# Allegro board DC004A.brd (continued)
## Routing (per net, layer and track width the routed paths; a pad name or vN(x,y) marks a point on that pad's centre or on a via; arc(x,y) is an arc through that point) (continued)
JESD_SYSREFP: length 5.2
  BOTTOM w0.152: R59.1 107.06,127.1 R62.1 106.07,127.1 105.88,126.91 105.49,126.91 104.71,127.68 103.24,127.68 103.13,127.79 U4.3
LMK04828_CSB: length 91.3
  TOP w0.152: SJP9.2 73.15,52.7 73.66,52.2 77.6,52.2 TP5.1
  L10_SIG-2 w0.152: v1(101.3,117.09) 101.27,74.48 v1(95.76,68.96)
  BOTTOM w0.152: v1(95.76,68.96) 95.76,59.82 94.49,58.55 94.49,55.88 92.96,54.36 79.88,54.36 77.72,52.2 TP5.1
  BOTTOM w0.279: U4.18 v1(101.3,117.09)
LMK04828_SYNC: length 4.1
  TOP w0.279: R97.2 132.08,93.73 v1(132.72,93.09)
LMK LOCKED:
  vias: v1(50.08,144.47)
LMK_CLKIN: length 6.1
  BOTTOM w0.279: R70.1 R71.1 J22.1
LMK_LMX_CLK: length 151.3
  TOP w0.152: SJP7.2 68.96,53.34 v1(68.96,58.2)
  TOP w0.279: v1(100.73,115.73) 80.54,115.73 75.06,121.22 75.06,125.34 68.55,131.85 62.41,131.85 61.93,132.33 v1(61.93,135)
  L10_SIG-2 w0.165: v1(61.93,135) 61.81,134.83 59.41,134.83 59.3,134.73 59,134.73 55.21,130.94 55.21,119.64 56.04,118.81 56.04,88.74 70.87,73.92 70.87,60.11 v1(68.96,58.2)
  BOTTOM w0.279: v1(61.93,135) 61.93,135.12 61.86,135.19 61.86,135.66 61.8,135.71 U3.16 ; U4.19 100.77,115.77 v1(100.73,115.73)
LMK_LMX_DATA: length 148.7
  L04_SIG-1 w0.14: v1(61.32,135.37) 61.32,134.8 62.23,133.88 68.7,133.88 77.64,124.94 77.64,119.2 85.71,111.13 95.43,111.13 99.67,115.37 v1(99.67,116.53)
  L10_SIG-2 w0.127: 72.17,53.75 72.17,74.06 64.73,81.5 64.73,132.42 62.48,134.67 62.48,135.19 62.2,135.48 61.43,135.48 v1(61.32,135.37)
  L10_SIG-2 w0.152: v1(71.12,52.7) 72.17,53.75
  BOTTOM w0.279: U3.17 61.3,135.38 v1(61.32,135.37) ; v1(99.67,116.53) 100.32,117.18 100.32,120.41 100.27,120.46 U4.20
LMK_SDO: length 117.2
  L10_SIG-2 w0.152: v1(105.16,69.47) 105.08,69.55 105.08,72.09
  L10_SIG-2 w0.165: 105.08,72.09 105.08,78.39 102.65,80.82 102.65,118.38 103.25,118.99 105.06,118.99 105.54,119.47 105.54,124.91 104.75,125.7 v1(104.75,126.44)
  BOTTOM w0.127: 79.12,50.16 80.01,51.05 95.12,51.05 97.92,53.85 97.92,67.56 99.31,68.96
  BOTTOM w0.152: 99.31,68.96 104.65,68.96 v1(105.16,69.47) ; 79.12,50.16 76.07,47.12 70.74,47.12 69.6,48.26 v1(69.6,49.02)
  BOTTOM w0.279: U4.5 104.4,126.79 v1(104.75,126.44)
LMX_CLKB: length 27.1
  L04_SIG-1 w0.14: v1(79.78,125.9) 79.78,120.01 v1(79.48,119.7)
  BOTTOM w0.279: C108.2 R52.2 64.32,131.69 69.75,126.26 76.58,126.26 76.94,125.9 v1(79.78,125.9)
LMX_CLKM: length 74
  BOTTOM w0.254: U3.22 57.96,137.61 arc(57.77,137.58) 57.61,137.47 arc(57.49,137.39) 57.34,137.36 R45.1 arc(56.71,137.47) 56.51,137.51 56.03,137.51 arc(56.01,137.51) 55.99,137.51 55.53,137.51 arc(55.24,137.45) 54.99,137.29 arc(54.71,137.1) 54.38,137.03 54.28,137.03 arc(53.92,137.1) 53.62,137.31 arc(53.39,137.46) 53.13,137.51 52.32,137.51 arc(51.94,137.44) 51.63,137.22 51.56,137.16 arc(51.35,137.02) 51.09,136.96 51.09,136.96 arc(50.69,137.04) 50.36,137.27 50.32,137.31 arc(50.09,137.46) 49.83,137.51 49.66,137.51 arc(49.3,137.44) 49,137.24 48.99,137.23 arc(48.77,137.08) 48.51,137.03 48.26,137.03 arc(47.97,137.09) 47.73,137.25 47.72,137.26 arc(47.45,137.44) 47.12,137.51 46.86,137.51 arc(46.65,137.47) 46.47,137.35 46.42,137.3 arc(46.07,137.07) 45.66,136.98 arc(45.32,137.05) 45.04,137.24 44.89,137.39 arc(44.65,137.48) 44.41,137.51 43.25,137.51 arc(41.97,137.26) 40.9,136.54 40.25,135.9 arc(40.07,135.63) 40.01,135.31 40.01,135.16 arc(39.95,134.87) 39.79,134.62 39.78,134.62 arc(39.49,134.42) 39.16,134.36 39.08,134.36 arc(38.74,134.29) 38.46,134.1 32.48,128.12 arc(32.41,128.02) 32.38,127.89 32.38,125.15 arc(31.83,123.8) 30.48,123.24 27.1,123.24 arc(25.57,122.94) 24.26,122.07 22.47,120.27 arc(20.75,117.69) 20.14,114.64 20.14,102.4 arc(20.23,101.93) 20.5,101.54 arc(20.69,101.26) 20.75,100.93 arc(20.69,100.6) 20.5,100.33 20.4,100.22 arc(20.22,100.14) 20.14,99.96 20.14,99.69 arc(20.22,99.29) 20.45,98.94 20.54,98.85 arc(20.7,98.62) 20.75,98.35 20.75,98.07 arc(20.7,97.81) 20.55,97.59 20.33,97.37 arc(20.19,97.05) 20.14,96.71 arc(20.32,96.29) 20.74,96.11 21,96.11 arc(21.1,96.13) 21.18,96.19 21.31,96.32 arc(21.39,96.37) 21.49,96.39 C50.1
LMX_CLKP: length 74
  BOTTOM w0.254: C51.1 21.49,95.12 arc(21.39,95.14) 21.31,95.2 21.18,95.33 arc(21.1,95.38) 21,95.4 20.74,95.4 arc(19.81,95.78) 19.43,96.71 19.43,114.64 arc(20.09,117.96) 21.97,120.78 23.76,122.57 arc(25.3,123.59) 27.1,123.95 30.48,123.95 arc(31.32,124.3) 31.67,125.15 31.67,127.89 arc(31.75,128.29) 31.98,128.63 38.39,135.04 39.33,135.98 40.39,137.04 arc(41.7,137.91) 43.25,138.22 56.5,138.22 arc(56.7,138.26) R44.1 57.35,138.37 arc(57.49,138.35) 57.6,138.27 arc(57.77,138.15) 57.98,138.11 U3.23
LMX_CSB: length 101.2
  L10_SIG-2 w0.127: v1(58.02,138.88) 60.13,136.77 65.54,136.77 66.65,135.66 66.65,131.15 65.97,130.48 65.97,87.23 78.2,75 78.2,56.47
  L10_SIG-2 w0.152: 78.2,56.47 74.43,52.7 v1(74.17,52.7)
  BOTTOM w0.127: v1(58.02,138.88) 58.28,138.61 U3.24
LMX_OSCM: length 46.8
  L10_SIG-2 w0.16: v1(69.61,135.13) 69.67,135.13 71.53,133.27 arc(72.06,132.48) 72.24,131.56 72.24,130.63 arc(72.46,129.51) 73.09,128.57 73.48,128.19 73.54,128.12 74.06,127.6 74.19,127.47 83.13,118.53 83.73,117.93 84.04,117.62 84.29,117.37 84.77,116.89 84.83,116.83 85.32,116.34 85.41,116.25 85.88,115.78 85.93,115.73 87.08,114.58 arc(89.09,113.24) 91.46,112.77 95.36,112.77 arc(96.4,113.2) 96.83,114.24 96.83,114.9 v1(96.88,114.94)
  BOTTOM w0.254: v1(69.61,135.13) 69.61,135.17 67.76,137.02 arc(67.33,137.3) 66.82,137.4 66.61,137.4 arc(66.5,137.42) 66.41,137.49 arc(66.27,137.58) 66.1,137.61 U3.9 ; C249.1 96.85,116.83 96.85,114.97 v1(96.88,114.94)
LMX_OSCP: length 47.3
  L10_SIG-2 w0.16: v1(96.12,114.94) 96.16,114.9 96.16,114.24 arc(95.93,113.67) 95.36,113.44 95.07,113.44 arc(94.97,113.46) 94.9,113.51 94.78,113.63 arc(94.6,113.75) 94.39,113.79 94.39,113.79 arc(94.19,113.75) 94.03,113.64 93.92,113.53 93.91,113.52 arc(93.82,113.46) 93.72,113.44 93.47,113.44 arc(93.37,113.46) 93.29,113.51 93.17,113.63 arc(92.96,113.77) 92.72,113.82 arc(92.46,113.77) 92.24,113.62 92.15,113.52 arc(92.05,113.46) 91.94,113.44 91.46,113.44 arc(89.35,113.86) 87.56,115.05 86.8,115.81 arc(86.75,115.88) 86.74,115.96 86.74,116.25 arc(86.69,116.46) 86.57,116.65 86.52,116.69 arc(86.31,116.84) 86.06,116.89 85.86,116.89 arc(85.73,116.91) 85.62,116.99 85.49,117.12 arc(85.42,117.23) 85.39,117.36 85.39,117.56 arc(85.34,117.8) 85.2,118.01 85.2,118.01 arc(85.04,118.12) 84.84,118.16 84.61,118.16 arc(84.5,118.19) 84.41,118.25 84.27,118.39 arc(84.19,118.5) 84.17,118.64 84.17,118.82 arc(84.11,119.09) 83.96,119.31 83.96,119.31 arc(83.77,119.44) 83.55,119.48 83.36,119.48 arc(83.14,119.53) 82.96,119.65 74.85,127.76 arc(74.78,127.86) 74.76,127.98 74.76,128.33 arc(74.74,128.43) 74.68,128.53 74.49,128.72 arc(74.4,128.77) 74.3,128.79 73.95,128.79 arc(73.83,128.82) 73.73,128.88 73.57,129.04 arc(73.08,129.77) 72.91,130.63 72.91,131.56 arc(72.68,132.74) 72.01,133.74 70.14,135.6 v1(70.14,135.67)
  BOTTOM w0.254: C250.1 96.14,116.83 96.14,114.97 v1(96.12,114.94) ; v1(70.14,135.67) 70.11,135.67 68.26,137.52 arc(67.6,137.96) 66.82,138.11 U3.8
LMX_SDO: length 104.4
  L10_SIG-2 w0.127: 73.34,52.64 76.97,56.27 76.97,62.76 75.99,63.74 75.99,71.92 65.41,82.51 65.41,135.5 64.62,136.28 60.47,136.28 59.19,135 57.44,135 v1(56.72,134.28)
  L10_SIG-2 w0.152: v1(71.12,49.02) 72.64,49.02 73.28,49.66 73.28,52.58 73.34,52.64
MASTER_BYPASS: length 3.8
  TOP w0.508: 80.39,39.37 79.07,40.69 SJP15.2
  vias: v1(80.14,36.96) v1(80.14,35.56) v1(80.64,36.2) v1(80.77,38.35) v1(81.28,39.37) v1(81.28,36.96) v1(81.28,35.56) v1(82.17,37.59) v1(82.27,39.12) v1(82.27,36.07)
MASTER_BYPASS1: length 10.2
  TOP w0.508: SJP16.3 87.86,44.3 v1(88.14,44.58) v1(85.98,44.58) v1(84.33,44.58) v1(82.93,44.58) v1(81.28,44.58) 81.1,44.4 SJP15.1
MUX_OUT: length 35.5
  TOP w0.279: v1(59.16,144.85) 57.87,146.14 49.72,146.14 48.56,144.97 48.56,135.29 50.05,133.79 56.24,133.79 56.76,133.28 57.46,133.28 57.74,133.56 v1(57.74,134.28)
  BOTTOM w0.254: R50.2 v1(59.16,144.85)
  BOTTOM w0.279: U3.20 57.75,134.28 v1(57.74,134.28)
NCOA0: length 102.5
  TOP w0.279: R11.1 v1(87.37,62.52)
  L04_SIG-1 w0.14: v1(44.58,76.07) 44.7,75.95 44.7,74.68 45.21,74.17 45.21,61.09
  L04_SIG-1 w0.152: 45.21,61.09 45.21,55.37 48.13,52.45 55.37,52.45 57.53,54.61 80.39,54.61 J7.2
  L10_SIG-2 w0.089: 36.7,88.39 36.32,88.77 36.32,89.79 35.94,90.17 35.94,91.31 35.56,91.69 34.16,91.69 33.91,91.95 33.91,101.73 34.43,102.24 v1(34.43,102.26)
  L10_SIG-2 w0.165: v1(44.58,76.07) 42.42,78.23 42.42,78.74 41.4,79.76 40.26,79.76 37.34,82.68 37.34,87.76 36.7,88.39 ; v1(87.37,62.52) 81.28,56.43 J7.2
NCOA1: length 89.8
  TOP w0.279: R12.1 v1(87.37,61.38)
  L10_SIG-2 w0.089: 37.72,88.39 36.96,89.15 36.96,92.58 36.83,92.71 35.18,92.71 34.93,92.96 34.93,100.58 34.43,101.08 v1(34.43,101.26)
  L10_SIG-2 w0.165: v1(48.77,75) 44.9,78.87 43.18,78.87 38.1,83.95 38.1,88.01 37.72,88.39 ; v1(87.37,61.38) 87.37,61.33 83.82,57.78 J7.4
  BOTTOM w0.152: v1(48.77,75) 56.64,75 57.09,75.45 60.25,75.45 60.7,75 73.03,75 73.03,74.8 76.71,71.12 81.79,71.12 83.82,69.09 83.82,66.42 85.6,64.64 85.6,63.15 v1(87.37,61.38)
NCOB0: length 84.6
  TOP w0.279: R17.1 v1(87.37,60.24)
  L10_SIG-2 w0.165: v1(87.37,60.24) 87.29,60.24 86.49,59.44 86.49,55.63 J7.6
  BOTTOM w0.152: v1(34.43,89.26) 34.43,89.08 34.57,89.08 34.57,84.56 35.56,83.57 35.56,73.41 36.45,72.52 45.08,72.52 45.19,72.42 54.01,72.42 55.72,74.13 56.98,74.13 57.47,74.62 59.88,74.62 60.64,73.85 72.96,73.85 76.33,70.48 81.53,70.48 82.04,69.98 82.04,68.58 83.31,67.31 83.31,64.52 84.71,63.12 85.09,63.12 86.71,61.5 86.71,60.89 v1(87.37,60.24)
NCOB1: length 86.9
  TOP w0.279: R18.1 v1(87.37,59.09)
  L10_SIG-2 w0.165: v1(87.37,59.09) 88.9,57.56 J7.8
  BOTTOM w0.152: v1(34.43,90.26) 34.29,90.12 34.29,89.72 34.24,89.72 33.97,89.45 33.97,89.07 34.24,88.8 34.29,88.8 34.29,84.67 34.29,84.33 35.28,83.34 35.28,73.29 35.31,73.26 35.31,72.39 35.56,72.14 54.9,72.14 55.79,73.02 73.03,73.02 76.2,69.85 80.13,69.85 80.39,70.1 80.77,70.1 80.79,70.08 80.95,70.08 81.66,69.37 81.66,68.45 82.55,67.56 82.55,64.39 84.14,62.8 84.14,59.5 84.54,59.09 v1(87.37,59.09)
OSC_M: length 17.8
  L04_SIG-1 w0.124: v1(91.47,125.42) 91.25,125.2 90.35,125.2 89.3,124.15 89.3,122.44 90.27,121.47 93.6,121.47 96.41,118.65 96.41,117.19 96.15,116.93 v1(95.55,116.93)
  BOTTOM w0.152: U4.41 92.71,125.29 92.6,125.18 91.71,125.18 v1(91.47,125.42)
OSC_P: length 17.9
  L04_SIG-1 w0.124: v1(91.47,124.66) 91.23,124.89 90.47,124.89 89.61,124.03 89.61,122.56 90.4,121.77 93.72,121.77 94.32,121.17 94.68,121.17 94.84,121.01 94.84,120.65 95.15,120.35 95.51,120.35 95.67,120.2 95.67,119.83 95.97,119.53 96.33,119.53 96.49,119.37 96.49,119.01 96.72,118.78 96.72,117.19 97.05,116.86 v1(97.49,116.86)
  BOTTOM w0.152: U4.40 92.71,124.79 92.6,124.9 91.71,124.9 v1(91.47,124.66)
OSCI: length 8.4
  TOP w0.152: Y2.2 50.78,67.07 C184.1 50.8,65.33 50.95,65.18 51.56,65.18 51.71,65.33 52.84,65.33 53.41,64.75 53.63,64.75 53.73,64.85 U8.2
OSCINN: length 4.7
  BOTTOM w0.152: C150.2 89.11,126.87 C152.2 90.1,126.87 90.29,126.68 92.6,126.68 92.71,126.79 U4.44
OSCINP: length 4.7
  BOTTOM w0.152: C145.2 89.11,126.21 C146.2 90.1,126.21 90.29,126.4 92.6,126.4 92.71,126.29 U4.43
OSCN: length 2.4
  BOTTOM w0.152: C149.2 86.21,126.87 R88.2 R93.1 87.78,126.92 C150.1
OSCO: length 8.4
  TOP w0.152: U8.3 53.73,64.35 53.61,64.47 53.3,64.47 52.72,65.05 51.83,65.05 51.68,64.9 50.98,64.9 50.8,64.72 50.8,62.99 50.78,62.97 Y2.1
OSCP: length 2.3
  BOTTOM w0.152: C144.2 86.16,126.21 R82.2 R85.1 87.78,126.16 C145.1
OVRA: length 58.3
  TOP w0.152: R225.1 96.27,65.91 97.28,66.93 v1(97.28,73.41)
  BOTTOM w0.152: 133.99,76.58 133.86,76.58 133.22,77.22 126.75,77.22 126.11,77.85 121.16,77.85 118.36,75.06 116.46,75.06 115.7,75.82 111.63,75.82 109.22,73.41 v1(97.28,73.41)
OVRA0: length 156.5
  TOP w0.152: v1(98.93,71.25) 98.3,70.61 98.3,63.75 95.58,61.04 D12.1
  L04_SIG-1 w0.127: 116.9,72.71 116.9,72.83 121.28,77.22 123.32,77.22 129.03,82.93 136.4,82.93 137.8,81.53 137.8,80.39 v1(135.25,77.85)
  L04_SIG-1 w0.14: v1(91.71,72.26) 91.27,72.7 91.27,74.4 88.33,77.33 62.88,77.33 v1(59.63,74.08) ; 115.38,71.18 116.9,72.71
  L04_SIG-1 w0.152: 115.38,71.18 99,71.18 v1(98.93,71.25) 98.87,71.18 92.78,71.18 v1(91.71,72.26)
  L10_SIG-2 w0.089: 35.78,102.62 v1(35.42,102.26)
  L10_SIG-2 w0.165: 35.78,102.62 35.92,102.76 35.92,103.11 37.34,104.52 50.71,104.52 55.03,100.2 55.03,87.81 59.63,83.21 v1(59.63,74.08)
OVRA1: length 87.8
  L04_SIG-1 w0.14: v1(91.71,71.12) 90.43,72.39 90.43,73.4 87.32,76.52 63.87,76.52 60.93,73.57 58.91,73.57 v1(58.44,74.04)
  L10_SIG-2 w0.089: 36.83,102.62 36.88,102.57 36.88,101.98 36.68,101.78 35.89,101.78 35.42,101.31 v1(35.42,101.26)
  L10_SIG-2 w0.165: 36.83,102.62 36.83,103.51 37.46,104.14 49.92,104.14 52.46,101.6 52.46,87.62 58.44,81.64 v1(58.44,74.04)
OVRB: length 61.1
  TOP w0.279: R226.1 v1(80.39,71.63)
  BOTTOM w0.152: v1(80.39,71.63) 81.41,71.63 84.52,74.74 94.3,74.74 96.39,72.64 110.87,72.64 111.25,73.03 111.25,74.55 112.14,75.44 115.32,75.44 116.2,74.55 118.62,74.55 121.41,77.34 125.48,77.34 126.94,75.88 133.41,75.88 133.99,75.31
OVRB0: length 199.3
  TOP w0.152: R145.2 v1(93.86,69.97) 95.12,68.71 95.12,66.64 94.84,66.36 86.48,66.36 85.21,67.64 85.21,70.99 81.75,74.44 75.88,74.44 74.62,73.18 56.19,73.18 v1(51.9,68.89) ; v1(113.16,70.36) 113.16,66.67 114.68,65.15 114.68,57.02 113.63,55.97 v1(113.46,55.97)
  L04_SIG-1 w0.152: v1(93.86,69.97) 95,69.97 95.12,69.85 97.92,69.85 98.42,70.36 v1(113.16,70.36)
  L10_SIG-2 w0.152: 35.31,88.14 35.31,89.14 v1(35.42,89.26) ; v1(113.46,55.97) 113.7,55.97 115.06,54.61 127.64,54.61 130.52,57.49 140.09,57.49 140.09,57.49 140.33,57.49 140.88,58.04 144.4,58.04 146.43,60.07 146.43,71.37 145.67,72.14 140.97,72.14 140.72,72.39 135.38,72.39 135.06,72.07 133.67,72.07 132.59,73.15 132.59,73.66 133.6,74.68 135.76,74.68 136.78,75.69 136.78,76.7 139.06,78.99 v1(139.06,79.12)
  L10_SIG-2 w0.165: v1(51.9,68.89) 43.88,68.89 42.16,70.61 37.21,70.61 34.8,73.03 34.8,79.63 35.31,80.14 35.31,88.14
OVRB1: length 80.4
  L04_SIG-1 w0.14: v1(51.05,74.04) 56.87,74.04
  L04_SIG-1 w0.152: 56.87,74.04 58.42,72.49
  L04_SIG-1 w0.165: 58.42,72.49 60.76,72.49 64.06,75.79 81.42,75.79 v1(84.39,72.82)
  L10_SIG-2 w0.089: 35.81,88.39 35.81,90.04 35.6,90.26 v1(35.42,90.26)
  L10_SIG-2 w0.165: v1(91.71,68.83) 90.82,68.83 86.83,72.82 v1(84.39,72.82) ; v1(51.05,74.04) 50.93,73.91 49.02,73.91 47.94,72.83 46.42,72.83 44.7,71.12 37.59,71.12 35.81,72.9 35.81,88.39
PD: length 32
  TOP w0.152: v1(36.45,86.49) 36.43,87.73 U1.P9
  L04_SIG-1 w0.14: J8.2 41.66,66.42 43.18,67.95 43.18,85.22 41.91,86.49 36.83,86.49
  L04_SIG-1 w0.152: 36.83,86.49 v1(36.45,86.49)
  BOTTOM w0.152: R21.1 J8.2
PG_RX1: length 17.5
  TOP w0.279: v3(136.53,110.87) 136.32,111.07 R104.2 134.24,113.87 122.76,113.87 J26.2
PG_U14: length 32.6
  TOP w0.279: v1(59.94,32) 59.18,32 58.42,31.24 U14.20
  BOTTOM w0.279: v1(59.94,32) 53.34,25.4 53.34,18.54 51.69,16.89 42.04,16.89 v1(40.51,15.37)
PLL2 LOCKED:
  vias: v1(50.08,136.09)
PRSNT_M2C_L: length 3.1
  TOP w0.279: R106.1 133.38,111.87 133.99,111.26 v1(133.99,109.6)
RFOUTB_M: length 3.9
  BOTTOM w0.279: C110.1 R49.1 58.98,134.32 60.3,135.65 U3.19
RFOUTB_P: length 4.1
  BOTTOM w0.279: C108.1 R48.1 61.73,134.4 61.7,134.4 61.56,134.54 61.39,134.72 61.14,134.72 60.86,135 60.86,135.06 60.77,135.14 60.77,136.31 U3.18
RFOUTBM: length 7.7
  TOP w0.279: J20.1 54.94,130.75 arc(55.43,130.85) 55.86,131.13 55.98,131.26 55.99,131.25 arc(56.48,131.58) 57.05,131.69 v1(58.98,131.69)
  BOTTOM w0.279: v1(58.98,131.69) C110.2
SLAVE_BYPASS:
  vias: v1(80.52,17.27) v1(81.41,18.16) v1(81.53,17.02) v1(82.27,17.91) v1(82.27,16.38) v1(82.27,14.86) v1(82.42,17.14) v1(82.42,15.62) v2(78.23,14.81)
SLAVE_BYPASS1: length 31.5
  TOP w0.279: v1(91.69,18.16) 91.69,19.18 92.08,19.56 92.58,19.56 93.73,20.7 99.7,20.7 100.84,19.56 100.84,16 102.74,14.1 106.81,14.1 108.71,12.19 R222.2
  TOP w0.508: v1(85.6,13.59) 85.47,13.72 81.15,13.72 80.64,14.22 80.64,14.43 SJP17.1
  vias: v1(86.36,14.35) v1(86.87,13.59) v1(87.76,14.35) v1(88.39,13.59) v1(89.03,14.48) v1(89.92,13.59) v1(90.04,18.16) v1(90.81,18.16) v1(90.81,14.48) v1(91.57,16.89) v1(91.57,15.88) v1(91.57,14.73) v1(91.57,13.59)
STAT 0:
  vias: v1(50.08,141.68)
STAT 1:
  vias: v1(50.08,138.88)
SYNC: length 124.8
  TOP w0.279: TP4.1 115.82,71.5 123.57,71.5 R98.1 ; v1(107.67,125.42) 109.04,125.42 110.62,123.84 110.62,119.13 116.71,113.03 v1(119.2,113.03) ; v1(129.47,92.41) 129.2,92.41 R97.1
  L04_SIG-1 w0.14: v1(129.47,92.41) 129.47,86.92 116.46,73.91 TP4.1 112.14,72.64 107.07,72.64 106.69,73.02 106.69,86.83 109.89,90.03 109.89,111 111.92,113.03 v1(119.2,113.03)
  BOTTOM w0.279: v1(107.67,125.42) 107.52,125.27 105.06,125.27 104.03,126.29 U4.6
SYNC_N: length 145.2
  TOP w0.254: R36.1 12.94,63.5 13.1,63.65 16.88,63.65 arc(16.9,63.65) 16.92,63.65 19.42,63.65 arc(20.11,63.51) 20.7,63.12 21.03,62.79 arc(21.79,62.28) 22.68,62.1 42.28,62.1 arc(43.11,62.27) 43.82,62.74 44.45,63.37 arc(45.01,64.22) 45.21,65.21 45.21,72.8 arc(45.39,73.71) 45.91,74.49 47.12,75.69 arc(48.07,76.33) 49.19,76.55 100.33,76.55 arc(101.08,76.4) 101.71,75.98 arc(102.84,75.23) 104.17,74.96 108.85,74.96 v1(108.88,74.94)
  L04_SIG-1 w0.16: v1(108.88,74.94) 108.93,74.98 109.26,74.98 arc(110.16,75.16) 110.92,75.67 113.59,78.34 arc(114.14,79.16) 114.33,80.13 114.33,81.79 arc(114.45,82.4) 114.8,82.92 119.88,88 arc(120.8,88.62) 121.89,88.83 122.53,88.83 arc(123.59,89.05) 124.49,89.65 129.39,94.55 arc(130.92,95.57) 132.73,95.93 134.96,95.93 v1(135.25,95.63)
SYNC_P: length 145.2
  TOP w0.254: R35.1 12.94,64.52 13.1,64.36 16.88,64.36 arc(16.91,64.36) 16.94,64.36 19.42,64.36 arc(20.38,64.17) 21.2,63.62 21.54,63.29 arc(22.06,62.94) 22.68,62.81 42.28,62.81 arc(42.84,62.93) 43.31,63.24 43.95,63.88 arc(44.36,64.49) 44.5,65.21 44.5,72.8 arc(44.74,73.98) 45.41,74.99 46.61,76.19 arc(47.8,76.99) 49.19,77.26 100.33,77.26 arc(101.35,77.06) 102.21,76.48 arc(103.11,75.88) 104.17,75.67 108.85,75.67 v1(108.88,75.7)
  L04_SIG-1 w0.16: v1(108.88,75.7) 108.93,75.65 109.26,75.65 arc(109.9,75.78) 110.45,76.15 113.11,78.81 arc(113.52,79.42) 113.66,80.13 113.66,81.79 arc(113.83,82.66) 114.32,83.39 119.41,88.48 arc(120.55,89.24) 121.89,89.51 122.53,89.51 arc(123.33,89.67) 124.01,90.12 128.92,95.02 arc(130.66,96.19) 132.73,96.6 134.96,96.6 v1(135.25,96.9)
SYNC_SE: length 257.2
  TOP w0.279: R98.2 126.62,73.03 129.69,73.03 129.96,73.29 130.39,73.29 130.66,73.03 133.73,73.03 v1(133.99,72.77)
  L04_SIG-1 w0.152: v1(26.67,44.32) 26.67,68.22 26.49,68.4 26.49,68.76 26.67,68.94 26.67,82.42 28.91,84.66 28.91,91.47 29.16,91.72 31.65,91.72 31.88,91.95 31.88,102.59 31.34,103.12 30.35,103.12 29.59,103.89 v1(24.26,103.89)
  L10_SIG-2 w0.165: v1(133.99,72.77) 134.62,73.41 145.41,73.41 147.07,71.75 147.07,59.44 145.16,57.53 140.78,57.53 140.45,57.2 140.21,57.2 139.97,57.2 131.11,57.2 127.76,53.85 112.52,53.85 109.73,51.05 109.73,38.61 107.06,35.94 96.65,35.94 93.73,33.02 81.66,33.02 80.26,31.62 74.17,31.62 73.28,32.51 37.34,32.51 36.32,33.53 27.56,33.53 25.65,35.43 25.65,38.1 26.16,38.61 26.16,43.81 v1(26.67,44.32)
  BOTTOM w0.152: 24.26,102.36 v1(24.26,103.89)
SYNC_SW: length 23.9
  TOP w0.279: U14.4 v1(40.89,27.43)
  BOTTOM w0.279: v1(40.51,11.56) 37.85,11.56 36.83,12.57 36.83,17.02 40.77,20.95 40.77,24.51 41.28,25.02 41.28,26.67 40.89,27.05 v1(40.89,27.43)
SYNCSE: length 4.6
  BOTTOM w0.152: R25.2 R26.1 27.36,102.36 27.94,101.78 28.91,101.78 v1(29.42,101.26)
SYS+: length 2
  TOP w0.279: C45.2 26.67,92.2 28.37,92.2 U1.L1
SYS-: length 2
  TOP w0.279: C47.2 26.67,91.31 28.37,91.31 U1.M1
SYSREF+: length 8.3
  BOTTOM w0.254: R76.1 107.53,119.25 R78.1 107.55,119.93 107.55,121.48 arc(107.13,122.49) 106.11,122.91 104.44,122.91 104.31,122.79 U4.13
SYSREF-: length 8.3
  BOTTOM w0.254: R77.1 106.86,119.25 R79.1 106.84,119.94 106.84,120.15 arc(106.73,120.42) 106.47,120.52 106.29,120.52 arc(106.07,120.62) 105.97,120.84 arc(106.06,121.04) 106.26,121.12 106.48,121.12 arc(106.73,121.23) 106.84,121.48 arc(106.62,121.99) 106.11,122.2 104.37,122.2 104.28,122.29 U4.14
SYSREFM: length 116
  TOP w0.254: v1(23.52,91.36) 23.54,91.38 25.05,91.38 arc(25.31,91.33) C47.1 ; v1(46.74,116.01) 46.95,115.8 arc(47.03,115.74) 47.13,115.72 49.56,115.72 arc(50.66,115.5) 51.59,114.88 51.59,114.88 arc(53.28,113.75) 55.27,113.36 104.54,113.36 arc(106.17,114.03) 106.84,115.65 106.84,116.21 v1(106.81,116.24)
  L10_SIG-2 w0.16: v1(23.52,91.36) 23.47,91.4 21.14,91.4 arc(19.57,92.05) 18.91,93.63 18.91,95.71 arc(19.2,97.16) 20.02,98.39 arc(20.63,98.8) 21.36,98.94 22.38,98.94 arc(23.59,99.45) 24.09,100.66 24.09,101.07 arc(24.29,102.05) 24.85,102.88 29.21,107.25 arc(29.99,107.77) 30.91,107.95 42.65,107.95 arc(42.83,107.99) 42.99,108.09 43.31,108.41 arc(43.4,108.51) 43.49,108.61 arc(43.54,108.68) 43.6,108.76 arc(43.79,109.1) 43.92,109.46 arc(43.97,109.76) 43.99,110.05 43.99,114.07 arc(44,114.16) 44,114.25 arc(44.15,114.73) 44.43,115.13 arc(45.07,115.55) 45.81,115.7 46,115.7 arc(46.4,115.78) v1(46.74,116.01)
  BOTTOM w0.254: R77.2 106.81,117.93 R80.1 106.84,117.85 106.84,116.26 v1(106.81,116.24)
SYSREFP: length 116
  TOP w0.254: v1(107.58,116.24) 107.55,116.21 107.55,115.65 arc(106.67,113.53) 104.54,112.65 61.94,112.65 61.94,112.65 58.21,112.65 arc(57.92,112.59) 57.68,112.43 arc(57.36,112.22) 56.98,112.14 56.68,112.14 arc(56.16,112.25) 55.71,112.54 arc(55.5,112.62) 55.27,112.65 arc(53.01,113.1) 51.08,114.38 arc(50.39,114.85) 49.56,115.01 47.13,115.01 arc(47.03,114.99) 46.95,114.94 v1(46.74,114.73) ; v1(23.52,92.12) 23.54,92.09 24.96,92.09 arc(25.27,92.15) C45.1
  L10_SIG-2 w0.16: v1(23.52,92.12) 23.47,92.07 21.14,92.07 arc(20.04,92.53) 19.58,93.63 19.58,95.71 arc(19.82,96.9) 20.5,97.92 arc(20.89,98.18) 21.36,98.27 22.38,98.27 arc(24.07,98.97) 24.77,100.66 24.77,101.07 arc(24.91,101.79) 25.32,102.41 29.68,106.77 arc(30.25,107.15) 30.91,107.28 42.65,107.28 arc(43.09,107.37) 43.46,107.62 44.37,108.53 arc(44.6,108.86) 44.68,109.26 44.68,110.38 arc(44.7,110.51) 44.77,110.61 44.9,110.74 44.9,110.74 45.04,110.87 arc(45.18,111.09) 45.24,111.35 arc(45.18,111.64) 45.01,111.89 arc(44.95,111.96) 44.89,112.03 arc(44.77,112.33) 44.89,112.64 45.09,112.83 arc(45.18,112.97) 45.21,113.13 45.21,113.24 arc(45.18,113.4) 45.09,113.53 44.88,113.75 arc(44.75,113.94) 44.7,114.17 arc(44.76,114.43) 44.91,114.66 arc(45.32,114.93) 45.82,115.03 46,115.03 arc(46.4,114.95) v1(46.74,114.73)
  BOTTOM w0.254: 107.55,117.85 107.58,117.88 R76.2 ; 107.55,117.85 R81.1 ; 107.55,117.85 107.55,116.26 v1(107.58,116.24)
TCRIT1: length 13.8
  TOP w0.152: U2.4 12.3,126.14 R28.2 R37.2 13.08,128.02 5.33,128.02 3.94,129.41 TP1.1
TCRIT2: length 7.9
  TOP w0.152: U2.7 7.7,125.64 R27.2 7.7,125.65 6.73,126.62 4.32,126.62 TP2.1
TDI: length 17.9
  BOTTOM w0.102: 128.52,74.8 138.3,74.8 J25.D30
  BOTTOM w0.279: 128.52,74.8 124.39,74.8 123.37,75.82 J27.1
TDIODE+: length 70
  TOP w0.152: R40.2 16.75,125.34 18.43,125.34 18.67,125.09 18.67,124.21
  L04_SIG-1 w0.089: v1(29.42,90.26) 29.79,89.89 30.26,89.89 30.27,89.88 30.58,89.88 30.59,89.89 31.26,89.89 31.27,89.88 31.58,89.88 31.59,89.89 32.26,89.89 32.27,89.88 32.58,89.88 32.59,89.89 32.74,89.89 33.02,90.17 33.02,91.59 33.17,91.74 33.83,91.74 33.99,91.9 33.99,102.62
  L04_SIG-1 w0.124: 18.67,124.21 18.67,125.2 18.79,125.32 19.93,125.32 20.05,125.2 20.05,124.97 20.18,124.84 21.12,124.84 21.24,124.97 21.24,125.2 21.37,125.32 22.31,125.32 22.43,125.2 22.43,125.02 22.58,124.87 23.48,124.87 23.63,125.02 23.63,125.2 23.75,125.32 26.26,125.32 29.34,128.4 30.85,128.4 30.98,128.27 30.98,128.14 31.13,127.99 32.02,127.99 32.17,128.14 32.17,128.27 32.29,128.4 36.07,128.4 37.47,127 37.47,121.03 35.69,119.25 35.69,108.97 34.29,107.57 34.29,102.92 33.99,102.62
TDIODE-: length 70
  TOP w0.152: R42.2 16.75,125.62 18.43,125.62 18.67,125.86 J17.1
  L04_SIG-1 w0.089: 34.98,102.62 34.98,92.02 34.7,91.74 34.24,91.74 33.83,91.34 33.83,90.07 33.4,89.63 32.86,89.63 32.85,89.62 32.7,89.62 32.69,89.61 32.16,89.61 32.15,89.62 31.7,89.62 31.69,89.61 31.35,89.61 30.61,88.87 30.23,88.87 29.84,89.26 v1(29.42,89.26)
  L04_SIG-1 w0.124: 34.98,102.62 34.59,103 34.59,107.44 35.99,108.84 35.99,119.13 37.77,120.9 37.77,127.13 36.19,128.7 29.21,128.7 26.14,125.63 18.79,125.63 18.67,125.75 J17.1
TDIODEN: length 3.6
  TOP w0.152: U2.3 13.33,125.64 C44.2 13.64,125.93 13.97,125.6 14.73,125.6 R42.1
TDIODEP: length 3.5
  TOP w0.152: U2.2 13.44,125.14 C44.1 13.68,124.93 14.07,125.32 14.76,125.32 R40.1
TDO: length 17.4
  BOTTOM w0.102: 128.52,73.28 138.56,73.28 J25.D31
  BOTTOM w0.279: J27.2 128.52,73.28
TMP461_SMBCLK: length 154
  TOP w0.152: U2.9 9.57,124.64 9.02,124.08 8.42,124.08 v1(7.7,123.35)
  L04_SIG-1 w0.14: 7.37,60.83 7.37,123.02 v1(7.7,123.35) ; 38.23,36.32 39.62,36.32 41.15,34.8 54.48,34.8 56.26,36.58 56.26,40.51 57.4,41.66 57.4,50.04 58.04,50.67 58.04,51.18 59.82,52.96 v1(59.82,53.09)
  L04_SIG-1 w0.152: 7.37,60.83 7.37,55.75 12.15,50.97 17.23,50.97 19.3,48.89 19.3,43.81 20.32,42.8 20.32,38.61 21.34,37.59 24.84,37.59 27.76,34.67 36.58,34.67 38.23,36.32
TMP461_SMBDAT: length 169.2
  TOP w0.152: v1(7.7,124.5) 8.55,124.5 9.18,125.14 U2.8
  TOP w0.279: R113.2 60.96,52.2 62.1,51.05 v1(65.79,51.05)
  L04_SIG-1 w0.14: v1(7.7,124.5) 6.98,123.78 6.98,123.65 6.86,123.78 6.5,123.78 6.26,123.53 6.26,123.18 6.5,122.93 6.86,122.93 6.98,123.06 6.98,55.24 15.75,46.48 ; v1(65.79,51.05) 65.66,51.05 64.39,49.78 64.39,35.31 63.37,34.29 38.23,34.29
  L04_SIG-1 w0.152: 15.75,46.48 15.75,38.35 18.29,35.81 21.46,35.81 21.97,35.31 26.66,35.31 27.63,34.34 30.81,34.34 31.37,33.78 37.72,33.78 38.23,34.29
  BOTTOM w0.279: R110.2 66.04,51.31 v1(65.79,51.05)
TMSP+: length 13
  TOP w0.279: J14.1 9.96,70.36 arc(10.91,69.96) 11.3,69.01 R34.1
TMSP-: length 13
  TOP w0.279: R38.1 11.3,59.02 arc(10.91,58.06) 9.94,57.66 J15.1
TMSTP+: length 46.2
  L04_SIG-1 w0.089: 27.56,100.12 27.57,100.12 27.61,100.08 28.01,100.08 28.03,100.09 arc(28.24,100.14) v1(28.43,100.26)
  L04_SIG-1 w0.16: v1(12.32,65.53) 12.32,64.5 arc(12.37,64.39) 12.48,64.34 14.16,64.34 arc(18,65.94) 19.6,69.78 19.6,81.46 arc(19.9,82.99) 20.77,84.28 23.49,87 arc(24.5,88.52) 24.86,90.31 24.86,93.4 arc(24.94,93.84) 25.19,94.21 25.31,94.33 arc(25.43,94.51) 25.48,94.73 25.48,98.82 arc(25.55,99.21) 25.78,99.55 26.04,99.81 arc(26.38,100.04) 26.77,100.12 27.56,100.12
TMSTP-: length 46.3
  L04_SIG-1 w0.089: 27.56,99.44 27.58,99.42 27.62,99.46 27.94,99.46 arc(28.2,99.41) v1(28.43,99.26)
  L04_SIG-1 w0.16: 27.56,99.44 26.77,99.44 arc(26.63,99.42) 26.52,99.34 26.25,99.07 arc(26.17,98.96) 26.15,98.82 26.15,94.73 arc(26.05,94.26) 25.79,93.86 25.67,93.74 arc(25.56,93.58) 25.53,93.4 25.53,90.31 arc(25.12,88.27) 23.96,86.53 21.24,83.81 arc(20.52,82.73) 20.27,81.46 20.27,69.78 arc(18.48,65.46) 14.16,63.67 12.48,63.67 arc(12.37,63.63) 12.32,63.51 v1(12.32,62.48)
V_BUS: length 25.8
  BOTTOM w0.508: v1(29.84,39.88) 29.84,42.55 40.37,53.07 46.46,53.07 JP6.3
  vias: v1(27.43,40.26) v1(27.43,38.1) v1(27.94,38.99) v1(28.45,39.62) v1(28.45,38.1) v1(28.83,38.86) v1(29.84,38.25)
VA11:
  vias: v1(15.88,87.93) v1(15.88,86.66) v1(16.64,87.3) v1(17.4,87.93) v1(17.4,86.66) v1(18.29,87.5) v1(18.29,86.36) v1(19.3,87.5) v1(19.3,86.36) v1(25.88,106.05) v1(29.42,97.26) v1(29.42,94.26) v1(30.43,99.26) v1(30.43,98.26) v1(30.43,97.26) v1(30.43,96.26) v1(30.43,95.26) v1(30.43,94.26) v1(30.43,93.26) v1(30.43,92.26) v1(83.82,20.45) v1(83.85,19.56) v1(84.96,20.45) v1(84.96,19.56) v1(85.6,18.16) v1(85.6,16.76) v1(85.6,15.49) v1(85.85,20.32) v1(86.23,18.67) v1(86.36,16.26) v1(86.49,19.43) v1(86.49,18.16) v1(86.74,20.32) v1(86.74,17.65) v1(87.25,16) v1(87.5,20.32) v1(87.5,15.49)
VA19: length 21.8
  TOP w0.254: C77.1 v1(27.18,89.41)
  BOTTOM w0.203: R19.1 37.72,71.37 34.93,68.58 v1(26.92,68.58)
  BOTTOM w0.254: C70.1 28.45,93.28 v1(28.43,93.26)
  BOTTOM w0.279: 28.63,87.16 27.81,86.34 ; 27.81,86.34 27.81,86.44 ; 27.81,86.34 C83.1 ; 27.83,87.19 27.81,87.18 27.81,86.44 ; 27.81,86.44 27.06,87.19
  BOTTOM w0.381: R20.1 v1(36.58,125.73)
  BOTTOM w0.508: v1(25.53,100.41) 26.31,100.41 26.82,99.9 C81.1
  vias: v1(27.05,87.76) v1(27.05,86.74) v1(27.05,86.11) v1(27.81,87.76) v1(28.43,98.26) v1(28.83,45.59) v1(29.42,100.26) v1(29.42,99.26) v1(29.42,98.26) v1(29.42,93.26) v1(29.42,92.26) v1(29.42,91.26) v1(30.43,100.26) v1(30.43,91.26) v1(31.42,100.26) v1(31.42,91.26) v1(32.43,100.26) v1(32.43,91.26) v1(81.28,49.66) v1(81.28,48.64) v1(82.17,49.15) v1(82.17,48.13) v1(83.82,49.66) v1(83.82,48.64) v1(84.71,49.15) v1(84.71,48.13) v1(86.36,49.66) v1(86.36,48.64) v1(87.25,49.15) v1(87.25,48.13) v1(88.9,49.66) v1(88.9,48.64) v1(89.79,49.15) v1(90.81,48.51) v1(91.69,49.02) v1(91.95,48.01) v1(92.71,49.53) v1(93.34,48.51) v1(94.23,49.02) v1(95,48.13) v1(95.12,38.1) v1(95.25,46.48) v1(95.25,44.32) v1(95.25,41.15) v1(95.25,39.37) v1(95.5,49.53) v1(95.5,42.42) v1(95.89,48.51) v1(95.89,40.89) v1(96.01,43.05) v1(96.01,38.1) v1(96.01,37.08) v1(96.14,46.99) v1(96.14,39.5) v1(96.27,45.21) v1(96.77,49.02) v1(96.9,42.93) v1(96.9,38.48) v1(96.9,36.96) v1(97,40.26) v1(97.16,47.88) v1(97.16,45.72) v1(97.16,41.4) v1(97.16,39.5) v1(97.28,44.32)
VADJ_RX: length 102.6
  TOP w0.279: R107.1 133.22,60.58 v1(133.99,61.34) ; v1(135.25,62.61) 134.77,62.13 134.77,61.59 134.73,61.56 134.73,61.13 134.77,61.09 134.77,60.3 135.51,59.56 135.51,58.17 135.13,57.78 133.48,57.78 132.21,56.52 118.75,56.52 117.35,55.12 PP17.1 ; v1(139.06,113.41) 137.44,111.79 R104.1
  L04_SIG-1 w0.14: v1(136.53,61.34) 138.18,59.69 145.54,59.69 148.59,62.74 148.59,69.88 148.55,69.93 148.55,70.28 148.59,70.32 148.59,72.42 148.55,72.47 148.55,72.82 148.59,72.86 148.59,82.2 148.55,82.25 148.55,82.6 148.59,82.64 148.59,84.74 148.55,84.79 148.55,85.14 148.59,85.18 148.59,94.78 148.55,94.82 148.55,95.17 148.59,95.22 148.59,97.32 148.55,97.36 148.55,97.71 148.59,97.76 148.59,106.71 148.55,106.76 148.55,107.11 148.59,107.15 148.59,109.25 148.55,109.3 148.55,109.65 148.59,109.69 148.59,111.12 146.3,113.41 v1(139.06,113.41)
  vias: v1(137.8,62.61)
VBIAS_VCO: length 2.4
  BOTTOM w0.305: C116.2 67.23,140.61 U3.3
VBIASBANK: length 2.6
  BOTTOM w0.127: v1(56.77,140.1) 56.77,140.13 C111.2
  BOTTOM w0.305: U3.27 58.05,140.11 57.69,140.48 C111.2
VD11: length 0.5
  BOTTOM w0.254: C93.1 38.43,91.36 v1(38.43,91.26)
  BOTTOM w0.279: C84.1 v1(37.42,100.26)
  vias: v1(37.03,68.91) v1(37.42,91.26) v1(37.92,68.78) v1(38.43,100.26) v1(38.81,69.17) v1(39.42,100.26) v1(39.42,99.26) v1(39.42,98.26) v1(39.42,97.26) v1(39.42,96.26) v1(39.42,95.26) v1(39.42,94.26) v1(39.42,93.26) v1(39.42,92.26) v1(39.42,91.26) v1(43.31,102.21) v1(45.19,125.67) v1(92.2,20.45) v1(95,18.67) v1(95.12,19.3) v1(95.12,16.76) v1(95.12,15.62) v1(95.5,17.65) v1(96.01,16.76) v1(96.01,15.62) v1(96.14,19.3) v1(96.14,18.16) v1(96.65,17.53) v1(96.9,15.75) v1(97,19.05) v1(97.03,18.16) v1(97.16,16.89)
VIO_B_M2C_RX:
  vias: v3(131.44,61.34) v3(132.72,62.61)
VPHY: length 4.3
  TOP w0.305: v1(53.21,64.01) 53.34,63.88 53.46,63.88 53.49,63.85 U8.4
  BOTTOM w0.254: v1(53.21,64.01) 53.09,64.14 53.09,64.39 ; FB12.2 53.09,64.39 ; 53.09,64.39 C169.1 C168.1
VREF_VCO1: length 2.5
  BOTTOM w0.305: U3.29 58.29,141.11 57.51,141.9 v1(57.51,142.54)
VREF_VCO2: length 2.8
  TOP w0.381: v1(62.3,143.36) 61.52,143.36 C115.2
  BOTTOM w0.305: U3.36 v1(62.3,143.36)
VREG_VCO: length 1.1
  BOTTOM w0.254: v1(63.38,143.49) 63.3,143.41 U3.38
VREGIN: length 26.2
  TOP w0.305: v1(62.03,67.69) 62.04,67.69 62.37,67.27 62.37,66.83 62.31,66.77 U8.50
  L10_SIG-2 w0.165: v1(62.03,67.69) 61.26,68.45 56.26,68.45 55.63,69.09 53.21,69.09 47.9,63.77 47.9,61.89 46.85,60.85 46.85,58.31 JP6.2
  BOTTOM w0.254: v1(62.03,67.69) C176.1
VTUNE: length 5.8
  BOTTOM w0.254: R55.2 C122.1
  BOTTOM w0.279: U3.35 61.8,143.12 61.78,143.14 61.78,143.57 61.8,143.59 61.8,144.16 62.22,144.58 62.33,144.58 62.37,144.53 62.8,144.53 62.85,144.58 64.46,144.58 64.5,144.53 64.63,144.53 C122.1
Y1_N: length 11.1
  BOTTOM w0.152: R91.1 84.2,126.89 R92.1 83.21,126.89 83.02,126.7 82.06,126.7 81.02,127.75 81.02,128.64 81.17,128.79 81.26,128.79 81.42,128.95 81.42,129.25 81.26,129.4 81.17,129.4 81.02,129.56 81.02,130.32 81.17,130.47 81.99,130.47 82.15,130.62 Y1.4
Y1_P: length 11.1
  BOTTOM w0.152: Y1.5 79.61,130.62 79.76,130.47 80.58,130.47 80.74,130.32 80.74,127.63 81.94,126.42 83.02,126.42 83.21,126.23 R84.1 84.2,126.23 R83.1
YO1_N: length 0.7
  BOTTOM w0.152: C149.1 R91.2
YO1_P: length 0.7
  BOTTOM w0.152: C144.1 R83.2
N18340257: length 0.5
  BOTTOM w0.254: v1(29.46,30.1) R148.2
N19884870: length 7.4
  BOTTOM w0.127: v3(77.07,133.67) 77.07,130.04 v1(77.12,129.99)
  BOTTOM w0.279: v3(77.07,133.67) 77.12,133.62 v1(77.12,129.99)
  vias: v1(77.07,128.98) v1(77.07,127.83) v1(78.08,128.98) v1(78.34,127.83)
N19884947: length 4.1
  BOTTOM w0.279: Y1.2 v1(79.61,145.36)
N19887754: length 2.1
  TOP w0.254: v1(92.18,125.8) 92.05,125.93 FB8.2
  BOTTOM w0.279: U4.42 92.19,125.79 v1(92.18,125.8)
N19887756: length 9.4
  TOP w0.381: FB9.1 v1(92.18,128.77) 92.18,129.48 v1(92.05,129.61)
  TOP w0.508: v1(90.65,130.75) 90.25,130.35 90.25,129.46 89.08,128.29 89.08,126.94 89.59,126.44 FB8.1
  BOTTOM w0.127: U4.47 93.44,128.29
  BOTTOM w0.279: 93.44,128.29 92.66,128.29 v1(92.18,128.77)
  vias: v1(90.65,133.29) v1(90.65,131.9) v1(91.39,132.66)
N19887760: length 3.5
  TOP w0.381: FB10.2 95.99,129.86 C165.1 v1(96.24,130.63)
  BOTTOM w0.127: U4.53 96.27,129.62 96.24,129.64 v1(96.24,130.63)
N19887762: length 3.2
  TOP w0.381: v1(101.96,131.01) 101.96,130.29 101.7,130.04 C166.1
  BOTTOM w0.279: v1(101.96,131.01) 101.77,130.82 U4.64
N19887789: length 67.4
  L04_SIG-1 w0.14: v1(84.99,142.29) 86.21,141.07 86.21,122.49 89.71,118.99 94.59,118.99 v1(94.95,118.71)
  L10_SIG-2 w0.165: v1(53.82,143.58) 56.38,143.58 56.74,143.94 60.8,143.94 61.96,142.78 68.67,142.78 68.93,143.03 80.21,143.03 80.96,142.29 v1(84.99,142.29)
  BOTTOM w0.279: v1(94.95,118.71) 94.77,118.82 U4.31 ; v1(53.82,143.58) 52.54,143.58 R102.2
N19887795: length 66.6
  L04_SIG-1 w0.14: v1(93.07,131.01) 91.94,132.14 91.94,133.52 87.62,137.84 87.62,141.66 86.33,142.95 75.66,142.95 72.39,146.22 52.47,146.22 51.21,144.96 51.21,134.89 v1(51.65,134.45)
  BOTTOM w0.127: U4.48 93.44,128.79
  BOTTOM w0.279: v1(93.07,131.01) 93.07,129.16 93.44,128.79 ; v1(51.65,134.45) R103.2
N19887804: length 56.2
  L10_SIG-2 w0.165: v1(54.21,139.64) 54.21,140.02 55.3,141.11 56.62,141.11 57.39,140.34 58.23,140.34 59.48,139.09 59.48,138.07 60.3,137.25 64.24,137.25 64.77,137.78 74.44,137.78 76.67,135.55 93.66,135.55 94.84,134.37 94.84,133.43 95.65,132.62 97.77,132.62 v1(99.27,131.12)
  BOTTOM w0.127: U4.59 99.27,129.62
  BOTTOM w0.279: v1(54.21,139.64) 52.42,139.64 R101.2 ; 99.27,129.62 v1(99.27,131.12)
N19887822: length 58.7
  L10_SIG-2 w0.165: v1(54.46,141.42) 54.46,141.47 54.96,141.97 57.47,141.97 58.43,141.02 59.6,141.02 60.13,141.55 65.8,141.55 66.95,140.41 84.36,140.41 88.65,136.11 97.83,136.11 99.21,134.73 99.21,133.59 100.29,132.52 100.29,131.13 99.58,130.42 v1(98.72,130.42)
  BOTTOM w0.279: v1(98.72,130.42) 98.77,130.37 U4.58 ; R100.2 51.71,141.68 52.51,140.88 53.91,140.88 v1(54.46,141.42)
N19887828: length 2.1
  TOP w0.381: v2(103.51,123.29) 103.13,123.29 C163.1
  BOTTOM w0.127: 102.6,123.29 U4.12
  BOTTOM w0.279: v2(103.51,123.29) 102.6,123.29
N19887830: length 2.5
  BOTTOM w0.127: 102.6,123.79 U4.11
  BOTTOM w0.203: 104.01,123.79 102.6,123.79
  BOTTOM w0.279: v1(104.62,124.4) 104.01,123.79
N19887836: length 4.6
  TOP w0.381: v1(103.47,124.29) 102.73,124.29 C154.2 ; C155.2 v1(93.45,120.72)
  BOTTOM w0.127: U4.10 102.6,124.29
  BOTTOM w0.254: v1(92.1,122.66) 92.14,122.66 92.26,122.79 93.44,122.79 ; 93.45,121.28 v1(93.45,120.72) ; 102.6,124.29 v1(103.47,124.29)
  BOTTOM w0.279: U4.36 93.44,122.79 ; U4.33 93.46,121.29 93.45,121.28
N19887876: length 2
  TOP w0.279: FB7.2 v1(92.18,124.33)
  BOTTOM w0.127: U4.39 93.44,124.29
  BOTTOM w0.254: v1(92.18,124.33) 92.21,124.33 92.25,124.29 93.44,124.29
N19887878: length 3.3
  TOP w0.508: FB9.2 90.91,127.92 91.48,127.34 v1(92.09,127.34)
  BOTTOM w0.127: U4.45 93.44,127.29
  BOTTOM w0.254: v1(92.09,127.34) 92.14,127.29 93.44,127.29
N19887910: length 1.1
  BOTTOM w0.279: U4.21 99.77,119.6 v1(99.8,119.58)
N19887912: length 1.1
  BOTTOM w0.279: U4.17 101.77,120.02 v1(102.08,119.7)
N19887930: length 1.2
  BOTTOM w0.279: v1(97.51,119.58) 97.27,119.82 U4.26
N19955835: length 12.9
  TOP w0.305: U13.4 24.32,35.74 25.02,35.04 25.02,30.99 26.42,29.59 26.42,25.91 26.8,25.53 v1(27.66,25.53)
N20234062: length 1.7
  TOP w0.279: C118.2 60.61,143.02 v1(60.8,143.22)
  BOTTOM w0.279: U3.33 v1(60.8,143.22)
N20239082: length 5.2
  TOP w0.279: v1(58.27,141.96) 57.99,141.83 54.98,141.83 54.64,142.18 R51.2
  BOTTOM w0.279: U3.30 58.72,141.61 v1(58.27,141.96)
N20251064: length 0.8
  BOTTOM w0.254: C120.2 R56.1
N20251377: length 1.7
  BOTTOM w0.229: R55.1 C121.1
  BOTTOM w0.254: R54.2 R55.1
N20258125: length 0.8
  TOP w0.381: D2.1 v1(58.5,144.44)
N20381922: length 1.9
  TOP w0.279: R130.2 53.19,58.84 53.21,58.82 53.64,58.82 53.66,58.84 U8.14
N20381931: length 3.8
  TOP w0.254: v1(52.58,62.87) 53,62.87 53.03,62.84 54.47,62.84 U8.6
  BOTTOM w0.254: v1(52.58,62.87) 53,62.87 53.03,62.84 53.45,62.84 53.48,62.87 R122.2
N20382558: length 3.5
  TOP w0.279: U9.4 78.97,68.01 R131.2 79.83,65.87 R123.2
N20382827: length 6.7
  TOP w0.152: R117.1 11.85,46.75 11.85,45.17 10.76,44.09 9.76,44.09 9.49,43.81 J31.3
N20382847: length 6.7
  TOP w0.152: J31.2 9.49,44.62 9.74,44.37 10.64,44.37 11.57,45.29 11.57,45.66 11.43,45.8 11.32,45.8 11.18,45.93 11.18,46.12 11.32,46.25 11.42,46.25 11.57,46.4 11.57,46.7 R116.1
N20392160:
  vias: v1(7.37,45.41) v1(8.15,45.41) v1(9.02,45.41) v1(13.46,40.39) v1(13.46,39.12) v1(13.59,43.18) v1(13.59,41.78) v1(14.2,38.58) v1(14.73,43.94) v1(14.73,42.42) v1(14.73,41.15) v1(14.73,40) v1(14.83,38.98) v1(14.86,38.23)
N20393078: length 1.7
  TOP w0.279: v1(52.45,73) 51.97,72.52 D7.2
N20442573: length 2.3
  TOP w0.279: R13.2 J7.1
N20442576: length 2.3
  TOP w0.279: R14.2 J7.3
N20442579: length 2.3
  TOP w0.279: R15.2 J7.5
N20442582: length 2.3
  TOP w0.279: R16.2 J7.7
N20446174: length 28.7
  L04_SIG-1 w0.089: 29.08,102.62 29.42,102.27 v1(29.42,102.26)
  L04_SIG-1 w0.14: TP9.1 16.26,117.6 16.26,106.3 19.3,103.25 28.45,103.25 29.08,102.62
N20447902: length 30.9
  TOP w0.152: R37.1 20.83,128.4 24,125.22 26.67,125.22 29.84,128.4 40.78,128.4 D1.2
N20475697: length 3.6
  TOP w0.279: U11.14 84.94,61.21 86.25,62.52 R138.1
N20475701: length 3.4
  TOP w0.279: U11.13 85,60.56 85.81,61.38 R139.1
N20475713: length 3.2
  TOP w0.279: U11.12 85.11,59.91 85.43,60.24 R140.1
N20475725: length 3.2
  TOP w0.279: R141.1 85.22,59.09 85.05,59.26 U11.11
N20475883: length 3.1
  TOP w0.279: U11.9 86.34,57.96 R142.1
N20476138: length 4.1
  TOP w0.508: R142.2 91.42,57.95 SJP14.1
N20477206: length 3.6
  TOP w0.279: U10.14 51.01,38.69 R133.1
N20477210: length 3.4
  TOP w0.279: U10.13 51.51,38.04 R134.1
N20477222: length 3.2
  TOP w0.279: U10.12 52,37.39 R135.1
N20477234: length 6.2
  TOP w0.279: R136.1 51.31,36.58 51.14,36.74 v1(50.38,36.74) U10.11
  BOTTOM w0.279: R132.2 50.27,39.24 50.55,38.96 50.55,36.91 v1(50.38,36.74)
N20477346: length 19.7
  TOP w0.152: U10.3 42.59,38.69 41.66,39.62 41.66,42.67 49.66,50.67 49.66,52.2 50.29,52.83 SJP3.2
N20477348: length 21.3
  TOP w0.127: v1(44.83,38.35) 44.52,38.04 U10.4
  TOP w0.152: v1(51.94,46.61) 51.94,52.2 SJP4.2
  L10_SIG-2 w0.127: 47.24,45.72 44.83,43.31 v1(44.83,38.35)
  L10_SIG-2 w0.152: 47.24,45.72 48.13,46.61 v1(51.94,46.61)
N20477350: length 24.3
  TOP w0.127: v1(45.85,38.23) 45.01,37.39 U10.5
  TOP w0.152: v1(53.09,45.72) 53.59,46.23 53.59,52.2 SJP5.2
  L10_SIG-2 w0.127: 51.05,45.72 49.78,44.45 46.61,44.45 45.21,43.05 45.21,38.86 v1(45.85,38.23)
  L10_SIG-2 w0.152: v1(53.09,45.72) 51.05,45.72
N20477352: length 29.3
  TOP w0.127: U10.6 v1(45.55,36.74)
  TOP w0.152: v1(55.37,38.61) 55.37,52.32 55.88,52.83 SJP6.2
  BOTTOM w0.127: 53.85,38.48 53.72,38.35 53.21,38.35 51.82,36.96 51.82,35.56 51.31,35.05 47.24,35.05 v1(45.55,36.74)
  BOTTOM w0.152: 53.85,38.48 55.25,38.48 v1(55.37,38.61)
N20477392: length 3.1
  TOP w0.279: R137.1 49.24,35.43 U10.9
N20478124: length 0.2
  TOP w0.152: U7.4 v1(67.06,51.88)
N20479286: length 3.6
  TOP w0.279: U12.14 89.38,70.95 R143.1
N20479288: length 3.4
  TOP w0.279: R144.1 89.87,70.3 U12.13
N20479290: length 3.2
  TOP w0.279: R145.1 90.37,69.65 U12.12
N20479292: length 3.2
  TOP w0.279: R146.1 90.52,69 U12.11
N20479340: length 3.1
  TOP w0.279: R147.1 90.68,67.7 U12.9
N20479396: length 1.6
  TOP w0.279: R147.2 93.33,67.69 SJP13.1
N20523656: length 84.2
  L10_SIG-2 w0.089: v1(36.43,101.26) 35.98,100.81 35.2,100.81 34.98,101.04 34.98,102.54 35.05,102.62
  L10_SIG-2 w0.165: TP10.1 23.24,124.33 36.96,124.33 37.97,125.35 40.89,125.35 41.53,125.98 42.55,125.98 43.43,126.87 54.23,126.87 54.92,126.18 54.92,121.92 53.21,120.21 53.21,105.54 52.71,105.03 37.34,105.03 35.05,102.74 35.05,102.62
N20560674:
  vias: v1(139.06,66.42) v1(139.06,63.88) v1(139.06,61.34) v1(140.34,62.61)
N20560927: length 17.5
  TOP w0.279: J26.1 125.44,112.39 128.45,109.39 133.1,109.39 133.62,108.86 137.06,108.86 v1(139.06,110.87)
N20597236: length 2
  TOP w0.279: R108.1 J30.2
N20601243: length 4.9
  TOP w0.279: D10.1 109.98,63.55 109.46,63.02 109.46,61.65 109.15,61.34 U15.7
N20601382: length 3.4
  TOP w0.279: D11.1 101.73,62.85 101.96,62.61 U15.1
N20601403:
  vias: v1(109.98,67.06)
N20601859:
  vias: v1(101.73,67.06)
N20602433: length 5.6
  TOP w0.279: U15.5 C14.2 R184.1 111.94,58.8 112.26,59.12 D9.2
N20603216: length 4.4
  TOP w0.279: D12.2 R31.1 C3.2 U15.3
N20603624: length 10.4
  TOP w0.279: R33.1 C4.2 R30.2 109.09,60.07 U15.6 106.05,60.07 104.78,61.34 U15.2
N20606076: length 1.7
  BOTTOM w0.254: R20.2 J9.1
N20606250: length 2.4
  BOTTOM w0.152: R19.2 J8.1
N20759391: length 5.6
  TOP w0.279: R197.1 R198.2 C261.2 24.77,150.75 U16.9
N20760406: length 5.6
  TOP w0.279: R199.1 R200.2 C266.2 25.53,136.53 U17.9
N20770678: length 6.5
  TOP w0.508: SJP17.3 76.2,13.69 77.98,11.91 v1(77.98,10.16) v1(77.98,9.02)
  vias: v1(73.91,7.77) v1(73.91,6.38) v1(75.82,7.77) v1(75.82,6.38) v1(77.6,7.26) v1(79.38,10.16) v1(79.38,9.02) v1(79.38,6.35) v1(79.5,7.26) v1(81.34,9.91) v1(81.34,8.64) v1(81.34,7.37) v1(81.34,6.1) v1(81.34,4.83)
N20770696: length 2
  TOP w0.381: C272.1 81.34,12.31 U19.1
N20770708: length 2
  TOP w0.279: U19.15 C273.1
N20770710:
  vias: v1(95.95,8.64) v1(95.95,7.37) v1(95.95,6.1) v1(95.95,4.83) v1(97.28,8) v1(97.28,6.73) v1(97.28,5.46) v1(98.6,9.91) v1(98.68,8.51) v1(98.81,4.83) v1(98.81,3.43) v1(99.06,11.05) v1(99.19,6.22) v1(100.46,10.92) v1(100.84,5.59) v1(100.84,3.81) v1(101.37,4.7) v1(101.85,1.52) v1(101.98,10.92) v1(101.98,5.59) v1(101.98,3.81) v1(102.62,6.35) v1(102.62,2.67) v1(103.51,10.92) v1(105.16,10.92) v1(106.68,10.92)
N20770722: length 5.2
  TOP w0.279: 95.95,2.29 97.66,2.29 98.42,1.52 R203.1
N20770740: length 2
  TOP w0.279: U19.7 R204.1
N20770762: length 22.9
  TOP w0.279: U19.10 v1(97.54,3.56)
  BOTTOM w0.279: v1(97.54,3.56) 94.49,3.56 92.41,1.47 82.09,1.47 79.38,4.19 v1(79.38,5.33)
N20770834: length 0.8
  TOP w0.279: v1(98.04,11.05) 97.66,11.05 ; v1(98.04,12.19) 97.66,12.19
  vias: v1(95.5,14.1) v1(95.63,12.57) v1(95.95,11.18) v1(96.9,12.57) v1(97.03,14.1) v1(97.92,14.22) v1(98.42,13.46)
N20771140: length 9.2
  TOP w0.279: R191.1 63.88,10.79 v1(64.26,10.41) ; v1(60.07,10.41) 59.05,11.43 U18.17
  BOTTOM w0.279: v1(60.07,10.41) 60.96,11.3 63.37,11.3 v1(64.26,10.41)
N20771180: length 1.6
  TOP w0.279: 62.36,14.22 61.98,13.84 R201.2
N20771182: length 3.6
  TOP w0.279: R201.1 59.94,12.45 ; 59.94,12.45 59.69,12.7 U18.18 ; 59.94,12.45 C271.1
N20771289: length 2.4
  TOP w0.279: U18.20 57.99,15.44 58.42,15.88 59.82,15.88 R190.2
N20771323: length 8.5
  TOP w0.254: R223.2 40.72,16.18 39.57,16.18 38.86,15.47 R196.2
  TOP w0.279: R223.2 R193.2 41.66,13.97 U18.2
N20771329: length 2.3
  TOP w0.279: U18.3 R195.1
N20771355: length 2.1
  TOP w0.279: C258.1 59.44,14.86 58.55,13.97 U18.19
N20771381: length 3.3
  TOP w0.279: 57.99,10.16 58.55,10.16 60.2,8.51 C251.1
N20771385:
  vias: v1(57.99,8.89) v1(57.99,7.62) v1(57.99,6.35) v1(57.99,5.08) v1(57.99,3.81) v1(59.82,4.95) v1(59.82,3.81) v1(60.96,4.95) v1(60.96,3.81) v1(61.85,5.97) v1(61.85,4.45) v1(62.1,3.56) v1(62.69,5.21) v1(63.5,5.97) v1(63.5,4.45) v1(63.75,3.56)
N20772111: length 8.6
  TOP w0.279: v1(63.75,26.42) 63.75,27.94 R211.1 ; U14.17 59.05,27.43 v1(60.07,26.42)
  BOTTOM w0.279: v1(60.07,26.42) 60.96,25.53 62.87,25.53 v1(63.75,26.42)
N20772147: length 1.6
  TOP w0.279: 62.36,30.23 61.98,29.84 R215.2
N20772149: length 3.6
  TOP w0.279: R215.1 59.94,28.45 ; 59.94,28.45 C216.1 ; 59.94,28.45 59.69,28.7 U14.18
N20772286: length 4.1
  TOP w0.254: R212.2 40.69,30.94 arc(40.56,31.13) R214.2
  TOP w0.279: U14.2 41.66,29.97 R212.2
N20772300: length 2.3
  TOP w0.279: U14.3 R213.2
N20772322: length 2.1
  TOP w0.279: U14.19 58.88,29.97 C215.1
N20772348: length 3.1
  TOP w0.279: U14.16 58.17,26.16 60.2,24.13
N20772352:
  vias: v1(57.91,19.05) v1(57.99,24.89) v1(57.99,23.62) v1(57.99,22.35) v1(57.99,21.08) v1(57.99,19.81) v1(59.44,19.05) v1(60.2,20.95) v1(60.2,19.94) v1(60.83,19.05) v1(61.85,21.97) v1(61.85,20.45) v1(62.23,19.05) v1(62.69,21.21) v1(63.5,21.97) v1(63.5,20.45) v1(63.63,19.05)
N20774965: length 13.3
  BOTTOM w0.508: v1(81.34,31.11) 79.5,32.96 79.5,35.43 78.05,36.88 78.05,41.66 v2(77.04,42.67)
  vias: v1(79.38,27.56) v1(81.34,29.84) v1(81.34,28.57) v1(81.34,27.3) v1(81.34,26.04)
N20775006: length 2.4
  TOP w0.279: U20.1 81.34,33.9 C211.1
N20775018: length 2
  TOP w0.279: U20.15 C210.1
N20775020: length 15.3
  TOP w0.279: C127.1 v1(98.68,29.84)
  BOTTOM w0.508: v2(91.92,43.31) 91.92,41.55 92.46,41.02 92.46,33.34 v1(95.95,29.84)
  vias: v1(95.95,28.57) v1(95.95,27.3) v1(95.95,26.04) v1(97.47,29.84) v1(97.47,28.57) v1(97.47,27.3) v1(97.47,26.04) v1(98.6,31.11) v1(98.68,27.94) v1(98.68,26.54) v1(99.06,32.26) v1(99.7,27.05) v1(99.7,25.15) v1(100.36,26.16) v1(100.84,22.99) v1(101.09,27.05) v1(101.09,25.27) v1(101.09,24)
N20775032: length 4.1
  TOP w0.279: U20.9 99.31,23.49 R216.1
N20775050: length 2
  TOP w0.279: U20.7 R217.1
N20775064: length 24.1
  TOP w0.279: v1(97.28,24.77) U20.10
  BOTTOM w0.279: v1(79.38,26.54) 79.38,25.78 80.39,24.77 80.39,22.61 81.15,21.84 93.6,21.84 96.52,24.77 v1(97.28,24.77)
N20775144:
  vias: v1(95.12,33.02) v1(95.95,32.38) v1(96.39,33.02) v1(97.03,35.31) v1(97.03,33.91) v1(97.16,32.38) v1(98.04,33.4) v1(98.04,32.26) v1(98.17,35.05) v1(98.93,35.05)
N20776452: length 1.5
  TOP w0.508: SJP16.2 89.89,42.06 v1(90.04,41.91)
  vias: v1(90.04,39.88) v1(90.04,38.86) v1(90.81,39.88) v1(90.81,38.86) v1(91.69,39.88) v1(91.69,38.86)
N20809211: length 2.2
  TOP w0.279: 65.66,63.75 65.25,63.35 U8.44
N20814533: length 2.4
  TOP w0.279: R224.1 41.66,11.43 U18.4
N20837548: length 5.8
  TOP w0.152: SJP7.3 69.66,53.78 69.66,58.48 R118.2
N20837573: length 7.5
  TOP w0.152: SJP8.3 71.12,58.17 R119.2
N20837587: length 8.4
  TOP w0.152: SJP9.3 72.64,55.37 72.26,55.75 72.26,57.91 70.99,59.18 R120.2
N20837623: length 10.4
  TOP w0.152: R121.2 71.37,62.61 72.01,61.98 72.01,59.05 73.53,57.53 73.53,56.26 74.17,55.63 SJP10.3
N20837793: length 19.4
  TOP w0.279: v1(65.89,62.85) 64.99,62.85 64.97,62.87 64.54,62.87 64.52,62.85 U8.43
  L10_SIG-2 w0.152: 67.69,51.05 67.69,50.55 68.71,49.53 70.61,49.53 v1(71.12,50.04)
  L10_SIG-2 w0.165: 67.69,51.05 67.69,61.05 v1(65.89,62.85)
N20837816: length 15.3
  L10_SIG-2 w0.152: 68.2,50.8 68.96,50.04 v1(69.6,50.04)
  L10_SIG-2 w0.165: v1(66.67,63.75) 68.2,62.23 68.2,50.8
N20965250: length 1.6
  TOP w0.152: R137.2 SJP2.1
N198851401: length 0.7
  BOTTOM w0.279: C131.2 88.7,128.98 R66.1
N198852420: length 1
  BOTTOM w0.279: R63.1 94.21,116.45 C128.2

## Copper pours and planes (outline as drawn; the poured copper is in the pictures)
1.538V on TOP: 69.6,1.02 69.6,3.94 67.56,3.94 67.56,8.25 61.6,8.25 61.6,11.05 62.74,11.05 62.74,9.27 67.56,9.27 67.56,11.56 64.64,11.56 64.64,12.83 67.56,12.83 67.56,17.65 75.31,17.65 75.95,18.29 77.47,18.29 77.47,15.24 75.31,13.08 72.01,13.08 72.01,5.84 76.33,5.84 76.45,5.71 76.45,3.3 74.3,3.3 74.3,1.02
1.538V on L08_PWR-2: 69.6,1.02 69.6,3.94 67.56,3.94 67.56,8.25 61.6,8.25 61.6,11.05 62.74,11.05 62.74,9.27 67.56,9.27 67.56,11.56 64.64,11.56 64.64,12.83 67.56,12.83 67.56,17.65 75.31,17.65 75.31,13.08 72.01,13.08 72.01,2.79 74.3,2.79 74.3,1.02
3.3VCLK on TOP, L06_PWR-1: 28.07,147.7 23.75,147.7 23.75,146.3 22.1,146.3 22.1,149.86 28.19,149.86 28.19,150.24 36.32,150.24 36.32,147.7 31.62,147.7 31.62,144.15 28.07,144.15
3.3VLMX on TOP: 28.83,133.48 24.38,133.48 24.38,132.08 22.86,132.08 22.86,135.64 28.96,135.64 28.96,136.02 37.08,136.02 37.08,133.48 35.69,133.48 35.69,131.95 32.38,131.95 32.38,129.92 28.83,129.92
3.3VLMX on L06_PWR-1: 28.83,133.48 24.51,133.48 24.51,132.08 22.86,132.08 22.86,135.64 28.96,135.64 28.96,136.02 37.08,136.02 37.08,133.48 35.56,131.95 32.38,131.95 32.38,129.92 28.83,129.92
5.0V_IN on BOTTOM (solid shape): 25.84,25.17 22.03,25.17 22.03,29.69 25.84,29.69
5.0V_IN on TOP: 14.1,33.68 11.35,33.68 11.35,23.83 25.32,23.83 25.75,24.26 25.75,29.48 24.35,30.88 24.35,31.94 23.28,33.01 22.06,33.01 21.38,33.68 21.38,35.48 21.59,35.69 23.11,35.69 23.11,36.83 22.86,37.08 14.48,37.08 14.1,36.7
5.0V_IN on BOTTOM: 6.35,37.59 6.35,24.13 25.78,24.13 25.78,57.53 25.65,57.66 16.51,57.66 16.26,57.4 16.26,40 16.26,40 16.26,38.26 15.59,37.59
5.0V_IN on L08_PWR-2: 14.28,37.47 3.04,37.47 3.04,24.13 25.78,24.13 25.78,57.66 16.26,57.66 16.26,53.03 14.28,53.03 ; 1 cut-out
5VIN on TOP: 38.48,10.54 38.48,8.25 40.89,8.25 40.89,7.37 44.58,7.37 44.58,10.54
5VIN on TOP: 38.48,26.54 38.48,24.38 40.89,24.38 40.89,23.37 44.58,23.37 44.58,26.54
5VIN on TOP: 39.5,31.88 39.5,29.72 40.77,29.72 40.77,31.88
5VIN on TOP: 9.91,133.73 9.91,135.76 6.73,135.76 6.73,138.81 9.91,138.81 9.91,141.86 12.83,141.86 12.83,133.73
5VIN on TOP: 9.14,147.96 9.14,149.99 5.97,149.99 5.97,153.04 9.14,153.04 9.14,155.45 12.07,155.45 12.07,147.96
5VIN on TOP: 38.61,14.61 38.61,13.59 40.89,13.59 40.89,14.61
5VIN on BOTTOM: 26.8,26.29 26.8,30.1 25.53,30.1 25.53,33.15 34.42,33.15 35.81,31.75 35.81,28.57 35.18,27.94 34.42,27.94 34.04,28.32 30.23,28.32 30.23,26.29
